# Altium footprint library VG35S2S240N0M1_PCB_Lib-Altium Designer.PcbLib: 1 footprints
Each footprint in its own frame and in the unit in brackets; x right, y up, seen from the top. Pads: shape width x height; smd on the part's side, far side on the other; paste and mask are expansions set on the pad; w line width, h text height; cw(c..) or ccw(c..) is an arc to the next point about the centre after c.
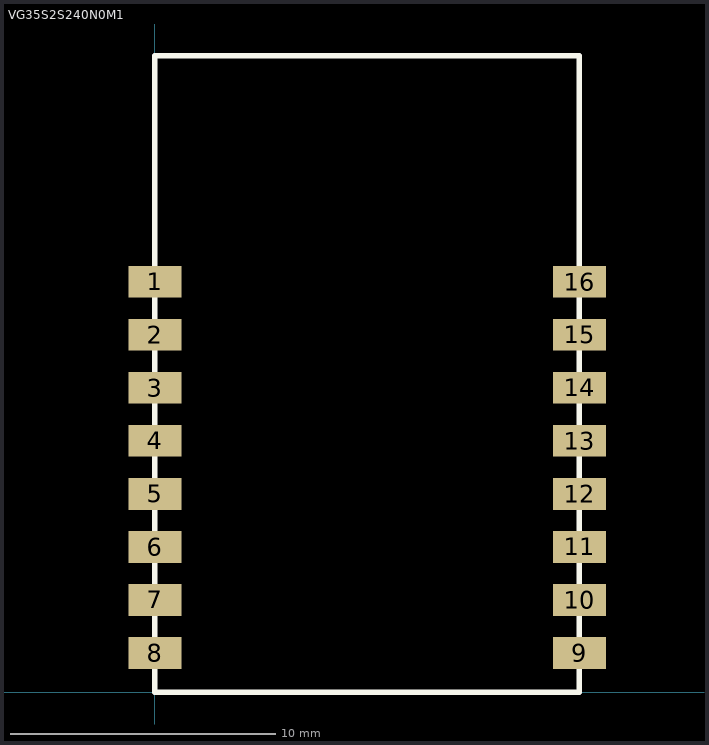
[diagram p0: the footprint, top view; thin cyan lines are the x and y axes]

## VG35S2S240N0M1 [mm]
pads (17):
  round 1.2 on Top Overlay: 1(-1.397,17.018)
  rect 2x1.2 smd: 1(0.01,15.48) 2(0.01,13.48) 3(0.01,11.48) 4(0.01,9.48) 5(0.01,7.48) 6(0.01,5.48) 7(0.01,3.48) 8(0.01,1.48) 9(16.02,1.48) 10(16.02,3.48) 11(16.02,5.48) 12(16.02,7.48) 13(16.02,9.48) 14(16.02,11.48) 15(16.02,13.48) 16(16.02,15.48)
Top Overlay:
  lines w0.2: 0,0 16.002,0 16.002,24 0,24 0,0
